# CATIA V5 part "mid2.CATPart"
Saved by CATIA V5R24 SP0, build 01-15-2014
Part number: Part1
Bounding box of the stored display mesh (mm): x -35.999 to 116.987, y -50 to 50, z -87.765 to 32
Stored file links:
  G:\내 드라이브\04_WORK\00_LECTURE\CAD2020\exam\mid2.CATPart
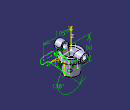
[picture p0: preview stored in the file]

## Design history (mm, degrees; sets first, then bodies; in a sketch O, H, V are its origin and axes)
AxisSystem1: origin (0, 0, 0), X (1, 0, 0), Y (0, 1, 0), Z (0, 0, 1)
Set1
  Sketch1 on ZX plane of AxisSystem1, origin (0, 0, 0), H (-1, 0, 0), V (0, 0, 1)
    circle A1 centre (0, 0) radius 15
    radius A1 = 15
Body1 (main body)
  Pad1: profile Sketch1, direction (0, 1, 0), length 50, mirrored extent
  Sketch2 on end face of Pad1, origin (-1.7978, 50, 4.6353), H (1, 0, 0), V (0, 0, -1)
    point P1 (1.7978, 4.6353)
    reference projected circle E1 centre (1.7978, 4.6353) radius 15 from edge [face of Pad1 from Sketch1.A1 | end face of Pad1]
    concentricity: E1 P1
  Sketch3 on XY plane of AxisSystem1, origin (0, 0, 0), H (1, 0, 0), V (0, 1, 0)
    arc A1 centre (0, 0) radius 36 from (-12, 33.9411) to (-12, -33.9411) ccw
    line L1 (12, 40) -> (12, 33.9411)
    line L2 (12, -40) -> (-12, -40)
    line L3 (-12, -40) -> (-12, -33.9411)
    line L4 (-12, 40) -> (12, 40)
    point P6 (-12, 33.9411)
    arc A2 centre (0, 0) radius 36 from (12, -33.9411) to (12, 33.9411) ccw
    point P8 (12, -33.9411)
    line L5 (12, -33.9411) -> (12, -40)
    line L6 (-12, 33.9411) -> (-12, 40)
    radius A1 = 36
    distance L2 L4 = 80
    distance L1 L3 = 24
    vertical: L1 V, L3 V, L5 V, L6 V
    horizontal: L2 H, L4 H
    equidistance: L1 L3 O, L2 L4 O
    coincidence: L3 P6, L1 P8, A1 A2, L1 L5, L3 L6
  Pad2: profile Sketch3, direction (0, 0, -1), length 70, opposite side length -5
  Sketch4 on ZX plane of AxisSystem1, origin (0, 0, 0), H (1, 0, 0), V (0, 0, 1)
    line L1 (55.2864, -13.9766) -> (25, -25)
    point P2 (25, -25)
    line L2 (25, -25) -> (25, -71.856)
    reference projected line E1 (12, -70) -> (36, -70) from edge [end face of Pad2 | face of Pad2 from Sketch3.A2]
    distance L2 V = 25
    angle L2 L1 = 110
    distance P2 E1 = 45
    vertical: L2 V
  Groove1: profile Sketch4, axis axis of face of Pad2 from Sketch3.A2, angle 360
  Sketch5 on YZ plane of AxisSystem1, origin (0, 0, 0), H (0, 1, 0), V (0, 0, 1)
    arc A1 centre (61.9855, 16.618) radius 90 from (-28, 15) to (-15, -30) ccw
    point P2 (-28, 15)
    point P3 (-15, -30)
    line L1 (-15, -30) -> (-15, -71.2625)
    axis line L2 (0, 21.9861) -> (0, -75.8534)
    point P5 (0, 21.9861)
    distance P2 V = 28
    radius A1 = 90
    distance L1 V = 15
    distance H P3 = 30
    distance P2 H = 15
    vertical: L1 V, L2 V
    coincidence: P5 V
  Groove2: profile Sketch5, axis Sketch5.L2, angle 360
  Sketch6 on start face of Pad1, origin (-1.2469, -50, -7.9598), H (1, 0, 0), V (0, 0, 1)
    point P1 (1.2469, 7.9598)
    reference projected circle E1 centre (1.2469, 7.9598) radius 15 from edge [start face of Pad1 | face of Pad1 from Sketch1.A1]
    concentricity: E1 P1
  Hole1: placed by Sketch6, at (0, -50, 0) direction (0, 1, 0), diameter 18, through (limit type 3)
  Body2
    Sketch7 on ZX plane of AxisSystem1, origin (0, 0, 0), H (1, 0, 0), V (0, 0, 1)
      construction line L1 (75, 20) -> (105, 20)
      point P2 (105, 20)
      line L2 (75, 32) -> (105, 32)
      line L3 (105, 8) -> (91.5702, 8)
      arc A1 centre (105, 20) radius 12 from (105, 32) to (105, 8) cw
      arc A2 centre (75, 20) radius 12 from (63, 20) to (75, 32) cw
      arc A3 centre (51, 20) radius 12 from (51, 8) to (63, 20) ccw
      point P6 (51, 20)
      line L4 (51, 8) -> (42.7053, 8)
      line L5 (42.7053, 8) -> (31, -5)
      point P9 (31, -5)
      point P10 (8.4943, -78.3314)
      line L6 (8.4943, -78.3314) -> (25, -60)
      arc A4 centre (91.5702, -4) radius 12 from (82.6525, 4.0296) to (91.5702, 8) cw
      point P15 (31, -5)
      point P16 (31, -5)
      line L7 (31, -5) -> (8.4943, -29.9951)
      line L8 (8.4943, -29.9951) -> (8.4943, -78.3314)
      point P18 (8.4943, -78.3314)
      reference projected line E1 (12, -5) -> (36, -5) from edge [face of Pad2 from Sketch3.A2 | start face of Pad2]
      reference projected line E2 (36, -20.9963) -> (36, -5) from face of Pad2 from Sketch3.A2
      reference projected line E3 (-25, -70) -> (25, -70) from edge [end face of Pad2 | face of Groove1 from Sketch4.L2]
      reference projected line E4 (25, -70) -> (25, -25) from face of Groove1 from Sketch4.L2
      point P25 (25, -60)
      line L9 (25, -60) -> (82.6525, 4.0296)
      reference projected line E6 (-25, -70) -> (25, -70) from edge [end face of Pad2 | face of Groove1 from Sketch4.L2]
      distance L1 L2 = 12
      length L1 = 30
      distance P2 V = 105
      radius A3 = 12
      radius A4 = 12
      distance L1 E3 = 90
      angle L6 V = 138
      distance P25 E6 = 10
      distance E2 P9 = 5
      horizontal: L1 H, L4 H
      tangency: A1 L2, A2 L2, A1 L3, A2 L3, A3 A2, L4 A3, A4 L3, A4 L6
      parallelism: L6 L5, L7 L5
      coincidence: P15 L5, P10 P18, P9 E1, P15 P9, L6 L9, P25 E4, P6 L1, P16 P9
      vertical: L8 V
    Pad3: profile Sketch7, direction (0, -1, 0), length 5, mirrored extent
  Trim1: tool Body2, faces to remove face of Pad3 from Sketch7.L7
  Sketch8 on ZX plane of AxisSystem1, origin (0, 0, 0), H (1, 0, 0), V (0, 0, 1)
    construction line L1 (75, 20) -> (105, 20)
    line L2 (75, 32) -> (105, 32)
    line L3 (105, 8) -> (75, 8)
    arc A1 centre (105, 20) radius 12 from (105, 32) to (105, 8) cw
    arc A2 centre (75, 20) radius 12 from (75, 8) to (75, 32) cw
    reference projected arc E1 centre (105, 20) radius 12 from (105, 8) to (105, 32) ccw from edge [face of Pad3 from Sketch7.A1 | end face of Pad3]
    reference projected arc E2 centre (75, 20) radius 12 from (75, 32) to (63, 20) ccw from edge [face of Pad3 from Sketch7.A2 | end face of Pad3]
    distance L1 L2 = 12
    horizontal: L1 H
    tangency: A1 L2, A2 L2, A1 L3, A2 L3
    concentricity: A1 E1, A2 E2
  Pad4: profile Sketch8, direction (0, -1, 0), length 9, mirrored extent
  Sketch9 on end face of Pad4, origin (106.6058, -9, 20.4025), H (1, 0, 0), V (0, 0, 1)
    point P1 (-1.6058, -0.4025)
    reference projected arc E1 centre (-1.6058, -0.4025) radius 12 from (-1.6058, -12.4025) to (-1.6058, 11.5975) ccw from edge [face of Pad4 from Sketch8.A1 | end face of Pad4]
    concentricity: E1 P1
  Hole2: placed by Sketch9, at (105, -9, 20) direction (0, 1, 0), diameter 9, through (limit type 3)
  Sketch10 on end face of Pad4, origin (72.4917, -9, 21.8036), H (1, 0, 0), V (0, 0, 1)
    point P1 (2.5083, -1.8036)
    reference projected arc E1 centre (2.5083, -1.8036) radius 12 from (2.5083, 10.1964) to (2.5083, -13.8036) ccw from edge [face of Pad4 from Sketch8.A2 | end face of Pad4]
    concentricity: E1 P1
  Hole3: placed by Sketch10, at (75, -9, 20) direction (0, 1, 0), diameter 9, through (limit type 3)
  Fillet1: radius 6, on edge [face of Pad1 from Sketch1.A1 | start face of Pad2] (x2); edge [start face of Pad2 | face of Pad1 from Sketch1.A1] (x2)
